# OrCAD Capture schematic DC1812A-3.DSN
size A
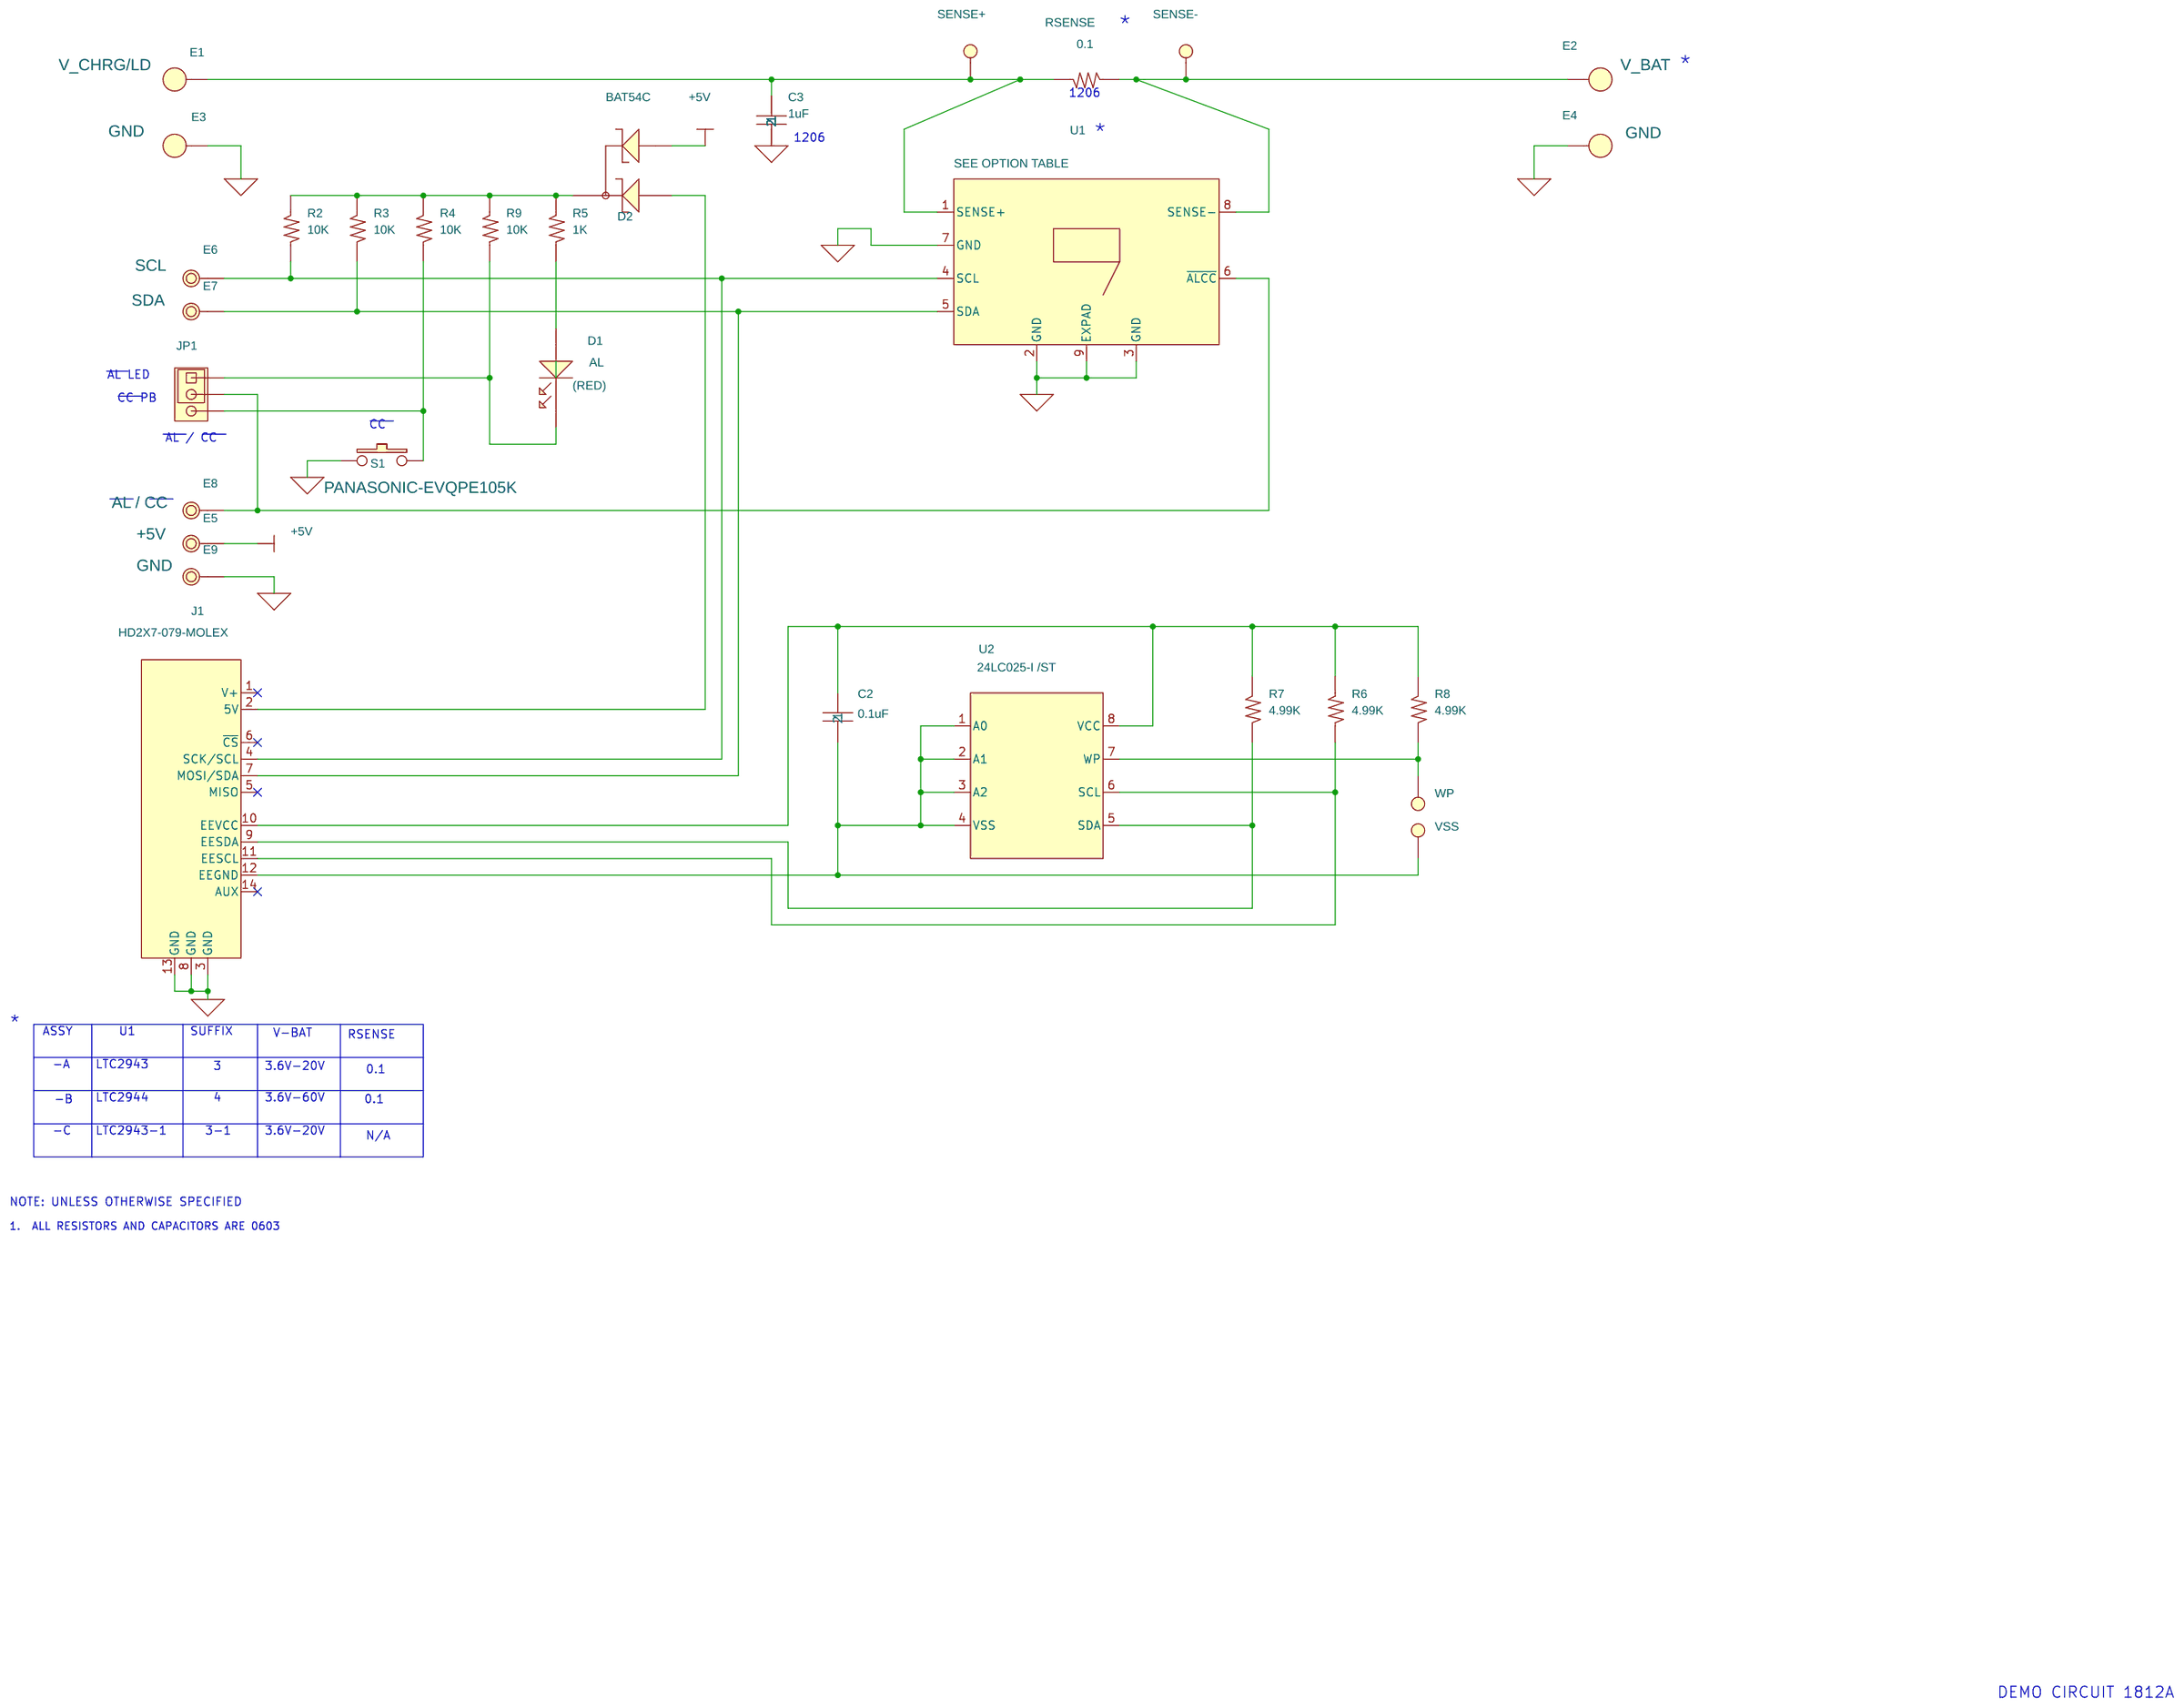
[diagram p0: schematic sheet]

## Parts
C2  0.1uF  [CC0603SMALL]
C3  1uF  [1206SMALL-NS]
D1  AL  [LED\PAN\LN1251C]
D2  BAT54C  [SOT23]
E1  PAD150-094  [PAD150-094]
E2  PAD150-094  [PAD150-094]
E3  PAD150-094  [PAD150-094]
E4  PAD150-094  [PAD150-094]
E5  PAD120-064  [PAD120-064]
E6  PAD120-064  [PAD120-064]
E7  PAD120-064  [PAD120-064]
E8  PAD120-064  [PAD120-064]
E9  PAD120-064  [PAD120-064]
J1  HD2X7-079-MOLEX  [HD2X7-079-MOLEX]
JP1  HD1X3-079  [HD1X3-079]
R2  10K  [CC0603SMALL]
R3  10K  [CC0603SMALL]
R4  10K  [CC0603SMALL]
R5  1K  [CC0603SMALL]
R6  4.99K  [CC0603SMALL]
R7  4.99K  [CC0603SMALL]
R8  4.99K  [CC0603SMALL]
R9  10K  [CC0603SMALL]
RSENSE  0.1  [1206SMALL-NS]
S1  PANASONIC-EVQPE105K  [EVQPE105K]
SENSE+  Pad  [PAD-50SMT]
SENSE-  Pad  [PAD-50SMT]
U1  SEE OPTION TABLE  [DFN8DD-NS]
U2  24LC025-I /ST  [TSSOP8]
VSS  Pad  [PAD70-70]
WP  Pad  [PAD70-70]

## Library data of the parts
C2 = CAP_NP: 1%: 25V; 1st Part Field: 50V; 2nd Part Field: 10%; 3rd Part Field: X7R; 4th Part Field: AVX; 5th Part Field: 12065C104KATM; 7th Part Field: CAP.,
C3 = CAP_NP_1: 1%: 25V; 1st Part Field: 50V; 2nd Part Field: 10%; 3rd Part Field: X7R; 4th Part Field: AVX; 5th Part Field: 12065C104KATM; 7th Part Field: CAP.,
D1 = LED_0: 10uH: (RED)
D2 = BAT54C-SCHOTTKY
E1 = E: VOLTAGE: V_CHRG/LD; VOLTAGE1: ??
E2 = E: VOLTAGE: ( 0 - 20V FOR LTC2943 ); VOLTAGE1: V_BAT
E3 E4 = E: VOLTAGE: GND
E5 = E-064: VOLTAGE: +5V
E6 = E-064: VOLTAGE: SCL
E7 = E-064: VOLTAGE: SDA
E8 = E-064: VOLTAGE: AL / CC
E9 = E-064: VOLTAGE: GND
J1 = HD2X7-079-MOLEX
JP1 = HD1X3
R2-R9 RSENSE = R
S1 = SW_PUSHBUTTON-SPST_SM_0
SENSE+ SENSE- VSS WP = E_1: 1st Part Field: LOW-PRO; 3rd Part Field: BANANA; 4th Part Field: KEYSTONE; 5th Part Field: 575-4; 7th Part Field: JACK,; 8th Part Field: BANJACK_575-4
U1 = LTC2944_0
U2 = 24LC025

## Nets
+5V: D2.2 E5.1(A)
SGND: C3.2 E3.1(A) E4.1(A) E9.1(A) J1.3(GND) J1.8(GND) J1.13(GND) S1.2 U1.2(GND) U1.3(GND) U1.7(GND) U1.9(EXPAD)
N17939563: C3.1 E1.1(A) RSENSE.2 SENSE+.1(A) U1.1(SENSE+)
N17939650: E6.1(A) J1.4(SCK/SCL) R2.2 U1.4(SCL)
N17939685: E2.1(A) RSENSE.1 SENSE-.1(A) U1.8(SENSE-)
N17939745: E8.1(A) JP1.2 U1.6(~{ALCC})
N17939844: D1.2 JP1.1 R9.2
N17957718: D2.3 R2.1 R3.1 R4.1 R5.1 R9.1
N17971248: E7.1(A) J1.7(MOSI/SDA) R3.2 U1.5(SDA)
N17974362: D2.1 J1.2(5V)
N17975458: JP1.3 R4.2 S1.1
N17976910: D1.1 R5.2
N18041968: C2.2 J1.12(EEGND) U2.1(A0) U2.2(A1) U2.3(A2) U2.4(VSS) VSS.1(A)
N18045809: C2.1 J1.10(EEVCC) R6.1 R7.1 R8.1 U2.8(VCC)
N18050073: R8.2 U2.7(WP) WP.1(A)
N18051810: J1.9(EESDA) R7.2 U2.5(SDA)
N18054319: J1.11(EESCL) R6.2 U2.6(SCL)

Not connected (* = marked no-connect by the designer): J1 1(V+)* 5(MISO)* 6(~{CS})* 14(AUX)*

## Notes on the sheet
- *
- *
- 1206
- 1206
- *
- AL LED
- CC PB
- AL / CC
- CC
- *
- ASSY
- U1
- SUFFIX
- V-BAT
- RSENSE
- -A
- LTC2943
- 3
- 3.6V-20V
- 0.1
- -B
- LTC2944
- 4
- 3.6V-60V
- 0.1
- -C
- LTC2943-1
- 3-1
- 3.6V-20V
- N/A
- NOTE: UNLESS OTHERWISE SPECIFIED
- 1.  ALL RESISTORS AND CAPACITORS ARE 0603
- DEMO CIRCUIT 1812A
